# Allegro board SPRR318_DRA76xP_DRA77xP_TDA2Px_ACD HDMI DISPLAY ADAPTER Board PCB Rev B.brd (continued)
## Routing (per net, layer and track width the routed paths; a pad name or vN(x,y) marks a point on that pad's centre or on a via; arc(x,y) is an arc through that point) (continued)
N16882731: length 3.5
  TOP w0.127: U19.4 65.67,49.51 RJ11.3 RJ10.3
N24600234: length 67.7
  TOP w0.127: R10.1 61.85,11.81 61.98,11.94 R20.1 63.27,11.4 64.8,11.4 65.15,11.05 65.15,7.24 63.12,5.21 54.1,5.21 53.21,6.1 49.02,6.1 47.37,4.45 v1(47.37,3.17)
  BOTTOM w0.127: v1(47.37,3.17) 45.59,1.4 11.81,1.4 11.37,1.83 U20.2
N24600238: length 71
  TOP w0.127: R9.1 61.6,12.95 61.79,12.76 62.42,12.76 R21.1 63.35,12.47 65,12.47 65.66,11.81 65.66,7.11 63.37,4.83 53.72,4.83 52.96,5.59 49.15,5.59 48.01,4.45 48.01,2.79 v1(47.5,2.29)
  BOTTOM w0.127: U20.3 10.72,1.85 11.68,0.89 46.1,0.89 v1(47.5,2.29)

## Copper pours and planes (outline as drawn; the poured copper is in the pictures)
GND on TOP (solid shape): 43.81,11.81 33.66,11.81 33.66,21.97 43.81,21.97
GND on TOP, BOTTOM, L2-GND1, L5-GND2: 45.09,27.3 45.09,57.78 67.94,57.78 67.94,0.64 0.64,0.64 0.64,27.3
GND on L4-SIGNAL: 10.67,0.64 0.64,0.64 0.64,27.3 23.37,27.3 23.37,19.68 26.29,16.76 22.73,16.76 20.95,14.99 20.95,12.95 21.21,12.7 30.35,12.7 32.38,10.67 45.21,10.67 47.5,12.95 47.5,14.99 61.34,14.99 62.8,13.53 62.8,7.68 62.87,7.62 62.87,5.84 60.58,3.56 11.81,3.56 10.67,2.41
VBUS2 on BOTTOM: 51.18,31.37 60.33,31.37 62.36,33.4 62.36,36.32 61.47,37.21 61.34,37.21 59.72,38.83 52.48,38.83 50.74,37.08 50.74,31.81
VBUS_AUX on BOTTOM: 52.45,45.72 61.59,45.72 62.61,46.74 62.61,53.21 60.33,55.5 54.74,55.5 51.69,52.45 51.69,46.48
V_DVDD on TOP: 49.53,24.26 49.53,20.57 46.35,17.4 46.35,15.11 45.85,14.61 44.83,14.61 44.32,15.11 44.32,23.62 44.7,24 47.75,24 48.26,24.51 49.28,24.51
V_DVDD on L4-SIGNAL: 45.72,15.75 46.48,15.75 46.99,15.24 46.99,13.08 44.96,11.05 32.77,11.05 32.07,11.75 32.07,13.08 32.8,13.81 43.78,13.81
V_PVDD on TOP: 38.35,6.6 43.43,6.6 44.07,7.24 44.07,10.67 43.31,11.43 41.91,11.43 41.66,11.18 41.66,9.27 41.15,8.76 38.73,8.76 38.1,8.13 38.1,6.86
V_TVDD on TOP: 30.73,6.6 34.67,6.6 35.18,7.11 35.18,8 36.2,9.02 39.5,9.02 40.01,9.53 40.01,10.41 40.39,10.79 41.02,10.79 41.27,11.05 41.27,11.43 41.15,11.56 40.01,11.56 39.88,11.43 33.02,11.43 32,10.41 32,9.14 31.5,8.64 30.99,8.64 30.35,8 30.35,6.99
VIO_3V3 on TOP: 28.32,5.71 28.32,4.32 28.7,3.94 31.24,3.94 31.88,4.57 31.88,5.84 31.62,6.1 28.7,6.1
VIO_3V3 on TOP: 35.94,5.71 35.94,4.32 36.32,3.94 38.86,3.94 39.5,4.57 39.5,5.84 39.24,6.1 36.32,6.1
VIO_3V3 on TOP: 48.39,25.02 51.18,25.02 51.56,25.4 51.56,26.54 51.05,27.05 48.77,27.05 48.13,26.42 48.13,25.27
VIO_3V3 on L3-SIGNAL: 45.09,27.3 45.09,57.78 67.94,57.78 67.94,0.64 0.64,0.64 0.64,27.3
VSYS_5V0 on L4-SIGNAL: 24.89,20.19 26.54,20.19 29.84,23.5 36.96,23.5 37.72,24.26 38.73,24.26 39.5,23.5 51.69,23.5 53.85,21.34 53.85,16.76 55.12,15.49 61.59,15.49 63.25,13.84 63.25,5.59 60.83,3.17 12.06,3.17 11.18,2.29 11.18,0.64 67.94,0.64 67.94,57.78 45.09,57.78 45.09,27.3 23.88,27.3 23.88,21.21

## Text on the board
BOTTOM: LAYER 6 | SOLDER
Board Geometry/Soldermask Bottom: BSM
Ref Des/Silkscreen Bottom: GND | FOR EVALUATION ONLY; | NOT FCC APPROVED FOR RESALE | ASSY 518570 REV | BSK
User.Comments: PWB 518571 REV B
TOP: PWB 518571 REV A | COMPONENT | LAYER 1
Ref Des/Assembly Top: CONN.CABLE
Board Geometry/Soldermask Top: TSM
Ref Des/Silkscreen Top: 1 | 2 | J6 PLUS HDMI DISPLAY ADAPTER | S/N | TSK
L2-GND1: LAYER 2 | GROUND
L3-SIGNAL: LAYER 3 | SIGNAL
L4-SIGNAL: LAYER 4 | SIGNAL
L5-GND2: LAYER 5 | GROUND
DIMENSION: SCORE LINE, 2 PLCS.
USER_PART_NUM_BOTTOM: BSLKC
USER_PART_NUM_TOP: TSLKC
DISPLAY_BOTTOM: SPS
DISPLAY_TOP: SPC
User.12: D14 | J1 | R122 | L44 | L50 | L41 | D8 | R124 | L39 | C221 | C223 | C149 | Cbst1 | C220 | C222 | C59 | C60 | C4 | C3 | C54 | C55 | C50 | C49 | D4 | C179 | C2 | C58 | C152 | C53 | C48 | L48 | L43 | L40 | C153 | L38 | R93 | R82 | C131 | C9 | C28 | R84 | C154 | R77 | R78 | C29 | C8 | C10 | L3 | C81 | C14 | C69 | C219 | C119 | C217 | C216 | C82 | C83 | C71 | C130 | C22 | C218 | C5 | C15 | C23 | C70 | C13 | C66 | R31 | C44 | C45 | C39 | C38 | L33 | L37 | L31 | R92 | L29 | C109 | C76 | R252 | Y1 | C89 | L13 | C88 | R230 | C203 | R235 | R240 | R245 | C94 | C77 | C78 | C92 | C93 | C79 | C91 | C90 | C201 | C200 | C202 | R243 | R233 | R238 | R228 | L32 | L36 | L30 | L28 | R62 | R232 | R237 | R247 | R242 | C286 | C256 | C271 | R244 | R239 | R229 | C199 | R234 | C196 | U16 | U22 | C197 | U23 | U26 | C198 | U25 | R231 | R236 | U24 | C259 | R241 | U20 | R246 | U18 | C295 | C250 | C265 | C244 | L47 | C280 | C274 | C289 | L68 | L54 | L61 | R185 | R184 | R226 | R227 | R212 | R213 | R198 | R199 | D3 | C182 | L35 | C30 | C34 | C18 | L34 | C33 | C24 | C32 | C17 | C16 | C31 | C105 | C106 | C99 | C43 | C37 | C104 | C98 | R251 | C97 | R33 | C75 | R32 | C74 | L27 | C296 | C300 | C304 | C308 | C301 | C305 | C309 | C297 | C302 | C306 | C310 | C298 | L26 | C303 | C307 | C311 | C299 | C241 | C279 | C249 | C264 | C294 | C275 | C245 | C260 | C290 | R20 | R19 | R18 | R17 | R16 | R15 | R14 | R12 | R13 | R11 | R10 | R48 | R9 | R8 | R47 | R7 | R6 | R5 | R4 | R3 | R2 | R1 | U8 | R74 | R73 | R75 | C148 | R76 | R79 | C151 | C150 | R83 | R80 | R81 | C120 | C121 | C65 | C64 | C63 | C114 | C115 | C116 | C111 | C110
User.16: TP16 | J3 | TP17 | TP12 | TP13 | TP14 | TP18 | TP15 | TP5 | TP6 | TP10 | TP8 | J2 | 1 | TP2 | GND | LCD CONNECTOR | TP3 | TP4 | VCC_LED | TP29 | TP11 | TP9 | TP7 | TP30 | J1 | VCC | P1 | TP31 | TP24 | TP19 | TP25 | TP20 | TP26 | TP21 | TP27 | TP22 | TP28 | TP23 | ANT2 | ANT1
User.17: COPY AND ROTATE IMAGE 180 DEGREES | COPY IMAGE | DATE | DESIGN ENGR | PROJECT ENGR | ENGR MGR | NEXT ASSEMBLY | APPROVED | CHECKED | DRAFTING | ENGR | NONE | 1 OF 1 | 1   TOTAL BOARD THICKNESS SHALL BE .062 +/- .007 INCHES. | 4.  SOLDERMASK ON BOTH SIDES OF THE BOARD SHALL BE S.M.O.B.C., LPI, COLOR: GREEN. | 3.  MINIMUM CLEARANCE ON THE BOARD SHALL BE .004 OF AN INCH. | 2.  COPPER PLATED SURFACE CONDUCTORS SHALL BE THE EQUIVALENT OF 1 OZ. COPPER | 9.  REFER TO STACKUP FOR CONTROLLED IMPEDANCES. | 8.  SURFACE FINISH SHALL BE IMMERSION GOLD. | 7.  FINISHED BOARD SHALL BE FREE OF BURRS ON EDGES. | 6.  DRC'S MUST BE RUN ON THE GERBERS BEFORE BUILDING BOARDS UNLESS PRIOR | 5.  PLATED THRU HOLE SIZE TOLERANCES SHALL BE +/- .003 INCH. | MINIMUM TRACE WIDTH ON THE BOARD SHALL BE .004 OF AN INCH. | AFTER PLATING.  PLANE LAYERS SHALL BE 1 OZ. COPPER.  AVERAGE COPPER ON | THE WALL OF THE PLATED HOLE SHALL BE .001 INCH. | ALL MATERIAL SHALL BE NEMA GRADE FR-4 OR EQUIVALENT, TG>=170C. | APPROVAL IS GIVEN IN WRITING. | UNPLATED THRU HOLE SIZE TOLERANCES SHALL BE +/- .002 INCH. | LAYER 1 | LAYER 2 | NOTES: UNLESS OTHERWISE SPECIFIED
User.18: DATE | DESIGN ENGR | PROJECT ENGR | ENGR MGR | NEXT ASSEMBLY | APPROVED | CHECKED | DRAFTING | ENGR | 1 OF 1 | ASSEMBLY SOLDER SIDE
User.19: AUSTIN,TEXAS 78756 | 4410 SHOALWOOD | (512)260-5778 | TURNING CONCEPT | INTO REALITY | NONE
User.20: AUSTIN,TEXAS 78756 | 4410 SHOALWOOD | (512)260-5778 | TURNING CONCEPT | INTO REALITY
User.22: 1. All board outlines shall be .020 in width. | 2. All other lines shall be .012 in width. | 3. Note and misc. text shall be text block 10. | 4. View and description text shall be text block 16. | 5. Make sure that there is not any double dimensioning, | label (REF) dim when needed.
User.28: FIGURE | SIZE | 10.0 | 12.0 | 13.0 | 40.0 | 51.0 | 95.0 | 22.0 | 93.0 | PLATED | NON-PLATED | DRILL CHART | ALL UNITS ARE IN MILS | QTY | 280 | 25 | 13 | 8 | 4 | 90 | 2 | 3 | TOL | NOTE
